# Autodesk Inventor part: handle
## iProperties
Author: Rich
Shininess: 41.0
PropertySet Name: _Private Model Information
Created: 2001-04
Part Number: handle
Document SubType Name: Modeling
Designer: Rich
Control State: 0
Master: False
Checked Out: False
PropertySet Name: Design Tracking Control
Density: 0.0
Volumn: 0.0
Area: 0.0
PropertySet Name: Model Information
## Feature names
1. Revolution1
2. Extrusion1
3. Extrusion2
4. Mirror1
